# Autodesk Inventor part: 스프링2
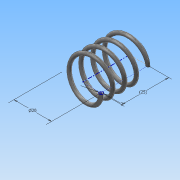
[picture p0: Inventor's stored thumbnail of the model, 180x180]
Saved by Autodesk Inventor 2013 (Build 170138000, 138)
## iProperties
Created: 2016-07
Part Number: 스프링2
Material: 스테인리스강
Document SubType Name: Modeling
Designer: Administrator
Mass: 6.22592 g
Surface Area: 15.7247 cm^2
Volume: 0.770534 cm^3
Density: 8.08 g/cm^3
Author: Administrator
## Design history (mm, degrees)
sketch "스케치1"
  geometry: L1 (0, 0)-(10, 0); L2 (10, 0)-(10, 19.5); L3 (10, 19.5)-(0, 19.5); L4 (0, 19.5)-(0, 0); C1 r 1 at (10, 0)
  constraints: 8 end point, 2 parallel, 1 centre point, 1 coincident, 1 horizontal, 1 perpendicular
  dimensions: "d0" = 20 diameter of L2 L4; "d2" = 2 diameter of C1; "d3" = 19.5 distance of L1.end L2.end (derived)
feature "코일1" pitch "d4" = 10; turns "d6" = 4; dims "d5" = 19.5 (= d3), "d7" = 0, angle "d8" = 90 deg, angle "d9" = 90 deg, "d10" = 0, "d11" = 0
sketch "스케치2"
  geometry: L1 (-11, 0)-(-9, 0) reference; 1 further point
  constraints: 1 horizontal alignment
extrude "돌출1" cut sketch "스케치2" distance "d12" = 10; taper "d13" = 0 deg
node "작업 평면1"
sketch "스케치3"
  geometry: L1 (11, 0)-(9, 0) reference; 1 further point
  constraints: 1 horizontal alignment
extrude "돌출2" cut sketch "스케치3" distance "d14" = 10; taper "d15" = 0 deg
node "솔리드1"
node "절단 모서리 투영1"
node "절단 모서리 투영2"
